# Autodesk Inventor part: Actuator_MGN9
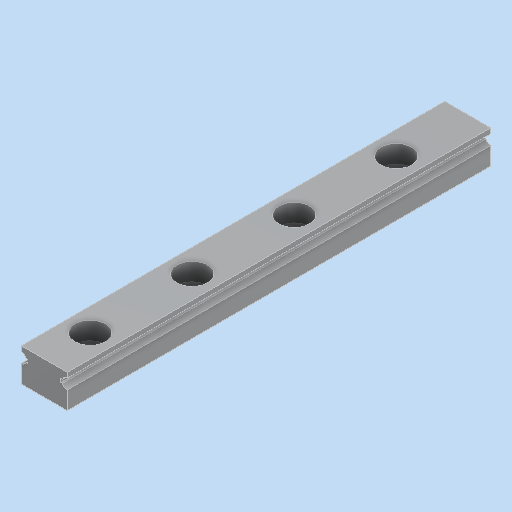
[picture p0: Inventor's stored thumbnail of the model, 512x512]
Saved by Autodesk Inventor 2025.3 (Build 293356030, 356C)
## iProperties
Created: 2016-10
Part Number: Actuator_MGN9
Material: Библиотека материалов (ГОСТ)|Сталь 40 ГОСТ 535-88
Document SubType Name: Modeling
Designer: R5800u
Density: 7.83 g/cm^3
Appearance: 104,107,110
Sending System: SolidWorks 2021
Last Author: Albert
Last Saved: 2021-07-29
Author: R5800u
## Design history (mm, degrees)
feature "LPattern1"
sketch "Schizzo1"
  geometry: L1 (9, -1)-(9, 0) reference; L2 (9, 0)-(0, 0) reference; L3 (0, 0)-(0, -1) reference; L4 (0.936, -1.648)-(1.265, -1.648) reference; L5 (1.265, -1.648)-(1.265, -2.352) reference; L6 (1.265, -2.352)-(0.936, -2.352) reference; L7 (0, -3)-(0, -6.5) reference; L8 (0, -6.5)-(9, -6.5) reference; L9 (9, -6.5)-(9, -3) reference; L10 (8.064, -2.352)-(7.735, -2.352) reference; L11 (7.735, -2.352)-(7.735, -1.648) reference; L12 (7.735, -1.648)-(8.064, -1.648) reference; A1 r 1 centre (0, -2) between (0.936, -1.648) and (0, -1) reference; A2 r 1 centre (0, -2) between (0, -3) and (0.936, -2.352) reference; A3 r 1 centre (9, -2) between (8.064, -2.352) and (9, -3) reference; A4 r 1 centre (9, -2) between (9, -1) and (8.064, -1.648) reference; 1 further point
extrude "Estrusione1" join sketch "Schizzo1" distance "d0" = 150; taper "d1" = 0 deg
node "Solido1"
node "Linea chiusa proiettata1"
